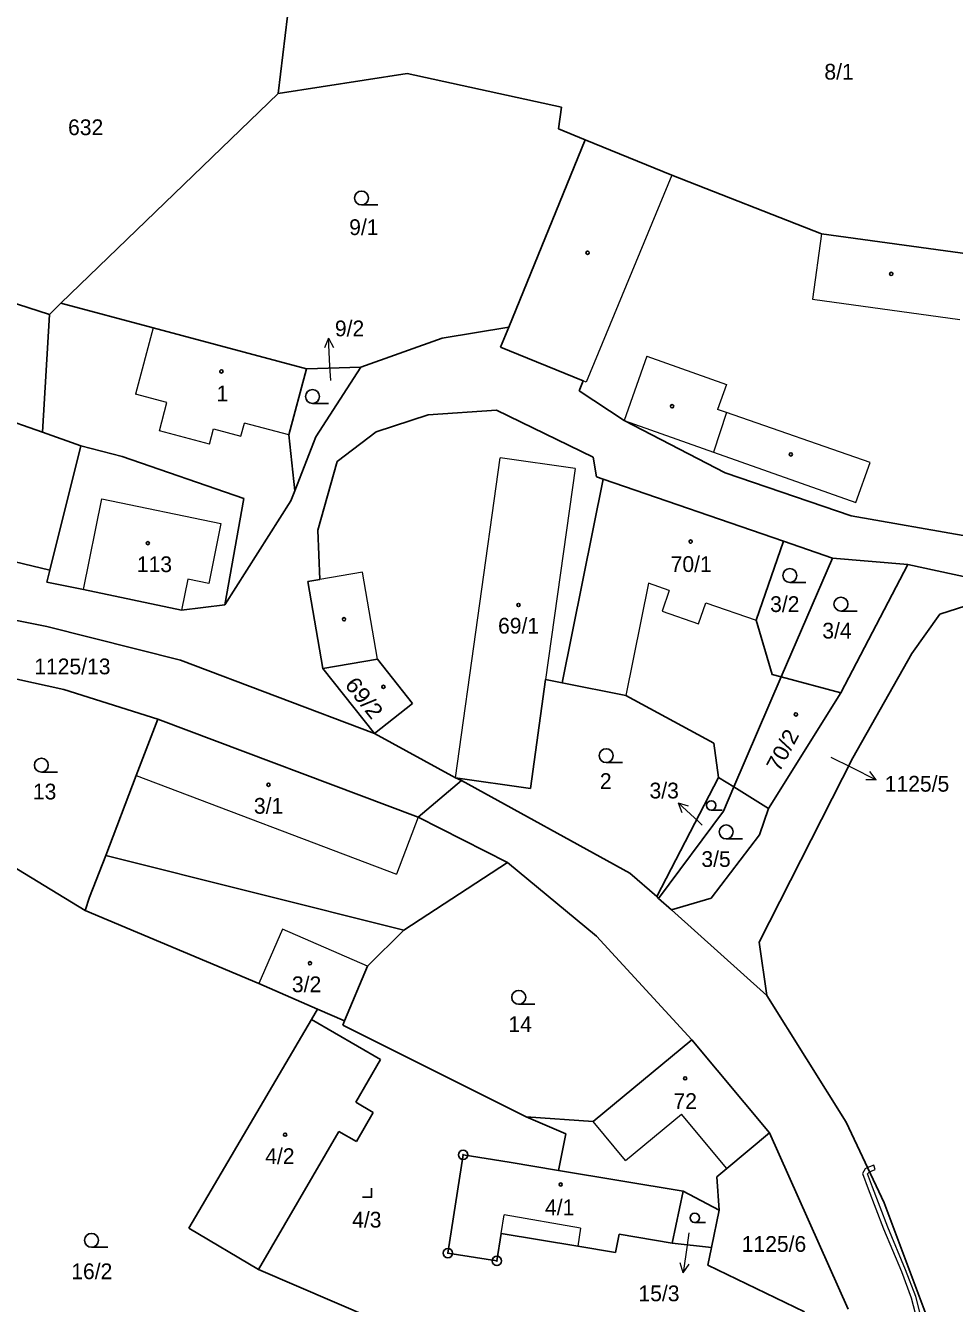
# Model space of a CAD drawing. Extents: x -765428 to -762163, y -1107632 to -1104975.
# Drawn here: x -764228.5 to -764128.3, y -1106034.3 to -1105896.5 of the extents above; entities that cross this region are included whole.
import ezdxf
from ezdxf.enums import TextEntityAlignment as Align

# ---------------------------------------------------------------- set-up
doc = ezdxf.new("R2010")
doc.units = 0
doc.header["$LTSCALE"] = 0.68
for name, color, linetype, lineweight in [('1', 7, 'Continuous', 25), ('13', 7, 'Continuous', 13), ('3', 7, 'Continuous', 25), ('4', 7, 'Continuous', 13), ('5', 7, 'Continuous', 25), ('7', 7, 'Continuous', 13), ('8', 7, 'Continuous', 25)]:
    doc.layers.add(name, color=color, linetype=linetype, lineweight=lineweight)
doc.layers.add('2', color=7, linetype='Continuous')

msp = doc.modelspace()

# ---------------------------------------------------------------- linework, layer by layer
at = {"layer": '1'}
for p, q in [((-764199.41, -1105888.5), (-764201.24, -1105903.77)), ((-764201.24, -1105903.77), (-764187.33, -1105901.63)), ((-764187.33, -1105901.63), (-764170.7, -1105905.25)), ((-764224.66, -1105926.41), (-764201.24, -1105903.77)), ((-764170.7, -1105905.25), (-764171.03, -1105907.61)), ((-764171.03, -1105907.61), (-764168.14, -1105908.79)), ((-764158.81, -1105912.59), (-764168.14, -1105908.79)), ((-764142.66, -1105918.92), (-764158.81, -1105912.59)), ((-764126.68, -1105921.13), (-764142.66, -1105918.92)), ((-764231.82, -1105925.72), (-764225.9, -1105927.61)), ((-764225.9, -1105927.61), (-764224.66, -1105926.41)), ((-764224.66, -1105926.41), (-764214.7, -1105929.07)), ((-764226.64, -1105940.33), (-764260.88, -1105928.31)), ((-764225.9, -1105927.61), (-764226.64, -1105940.33)), ((-764198.19, -1105933.47), (-764214.7, -1105929.07)), ((-764177.25, -1105931.16), (-764176.37, -1105929)), ((-764183.54, -1105930.16), (-764192.34, -1105933.29)), ((-764168.36, -1105934.78), (-764177.25, -1105931.16)), ((-764198.19, -1105933.47), (-764200.1, -1105940.62)), ((-764192.34, -1105933.29), (-764198.19, -1105933.47)), ((-764192.34, -1105933.29), (-764197.16, -1105940.83)), ((-764168.79, -1105935.85), (-764168.36, -1105934.78)), ((-764168.79, -1105935.85), (-764163.94, -1105939.06)), ((-764177.68, -1105937.93), (-764185.08, -1105938.43)), ((-764167.26, -1105943.02), (-764177.68, -1105937.93)), ((-764185.08, -1105938.43), (-764190.68, -1105940.28)), ((-764153.05, -1105944.69), (-764163.94, -1105939.06)), ((-764222.5, -1105941.78), (-764226.64, -1105940.33)), ((-764200.1, -1105940.62), (-764199.44, -1105946.63)), ((-764197.16, -1105940.83), (-764199.44, -1105946.63)), ((-764190.68, -1105940.28), (-764194.87, -1105943.49)), ((-764222.5, -1105941.78), (-764225.85, -1105955.21)), ((-764218.06, -1105942.93), (-764222.5, -1105941.78)), ((-764204.93, -1105947.46), (-764218.06, -1105942.93)), ((-764194.87, -1105943.49), (-764196.97, -1105950.9)), ((-764166.9, -1105945.13), (-764167.26, -1105943.02)), ((-764166.2, -1105945.37), (-764166.9, -1105945.13)), ((-764139.46, -1105949.34), (-764153.05, -1105944.69)), ((-764170.62, -1105967.34), (-764166.2, -1105945.37)), ((-764166.2, -1105945.37), (-764146.77, -1105952.07)), ((-764206.99, -1105958.94), (-764204.93, -1105947.46)), ((-764199.88, -1105947.74), (-764206.99, -1105958.94)), ((-764199.44, -1105946.63), (-764199.88, -1105947.74)), ((-764126.77, -1105951.58), (-764139.46, -1105949.34)), ((-764240.7, -1105951.61), (-764225.85, -1105955.21)), ((-764196.97, -1105950.9), (-764196.75, -1105956.21)), ((-764146.77, -1105952.07), (-764149.71, -1105960.6)), ((-764146.77, -1105952.07), (-764141.47, -1105953.9)), ((-764141.47, -1105953.9), (-764147, -1105966.72)), ((-764141.47, -1105953.9), (-764133.34, -1105954.59)), ((-764133.34, -1105954.59), (-764140.59, -1105968.43)), ((-764133.34, -1105954.59), (-764123.59, -1105956.71)), ((-764225.85, -1105955.21), (-764226.17, -1105956.48)), ((-764226.17, -1105956.48), (-764222.23, -1105957.3)), ((-764211.64, -1105959.51), (-764222.23, -1105957.3)), ((-764196.75, -1105956.21), (-764198.05, -1105956.44)), ((-764198.05, -1105956.44), (-764196.43, -1105965.81)), ((-764239.49, -1105958.6), (-764226.16, -1105961.28)), ((-764211.64, -1105959.51), (-764206.99, -1105958.94)), ((-764129.91, -1105959.96), (-764125.31, -1105958.48)), ((-764132.92, -1105964.2), (-764129.91, -1105959.96)), ((-764226.16, -1105961.28), (-764211.77, -1105964.9)), ((-764139.27, -1105975.43), (-764132.92, -1105964.2)), ((-764211.77, -1105964.9), (-764190.86, -1105972.83)), ((-764190.52, -1105964.79), (-764196.43, -1105965.81)), ((-764196.43, -1105965.81), (-764190.86, -1105972.83)), ((-764190.52, -1105964.79), (-764186.75, -1105969.57)), ((-764224.35, -1105968.07), (-764229.42, -1105966.96)), ((-764172.41, -1105966.98), (-764174.05, -1105978.74)), ((-764172.41, -1105966.98), (-764170.62, -1105967.34)), ((-764147, -1105966.72), (-764152.11, -1105978.58)), ((-764140.59, -1105968.43), (-764147, -1105966.72)), ((-764214.2, -1105971.28), (-764224.35, -1105968.07)), ((-764163.76, -1105968.72), (-764170.62, -1105967.34)), ((-764140.59, -1105968.43), (-764148.38, -1105980.91)), ((-764186.75, -1105969.57), (-764190.86, -1105972.83)), ((-764163.76, -1105968.72), (-764154.27, -1105973.85)), ((-764216.56, -1105977.35), (-764214.2, -1105971.28)), ((-764214.2, -1105971.28), (-764186.14, -1105981.85)), ((-764190.86, -1105972.83), (-764182.12, -1105977.61)), ((-764154.27, -1105973.85), (-764153.75, -1105977.56)), ((-764149.39, -1105995.34), (-764139.27, -1105975.43)), ((-764219.82, -1105985.97), (-764216.56, -1105977.35)), ((-764186.14, -1105981.85), (-764181.47, -1105977.89)), ((-764182.12, -1105977.61), (-764181.47, -1105977.89)), ((-764174.05, -1105978.74), (-764182.12, -1105977.61)), ((-764163.34, -1105987.9), (-764181.47, -1105977.89)), ((-764153.75, -1105977.56), (-764160.43, -1105990.42)), ((-764152.11, -1105978.58), (-764153.75, -1105977.56)), ((-764152.11, -1105978.58), (-764153.24, -1105981.19)), ((-764148.38, -1105980.91), (-764152.11, -1105978.58)), ((-764149.33, -1105983.77), (-764148.38, -1105980.91)), ((-764186.14, -1105981.85), (-764176.51, -1105986.72)), ((-764153.24, -1105981.19), (-764160.22, -1105990.61)), ((-764222.03, -1105991.92), (-764237.59, -1105982.48)), ((-764154.57, -1105990.6), (-764149.33, -1105983.77)), ((-764221.58, -1105990.48), (-764219.82, -1105985.97)), ((-764176.51, -1105986.72), (-764187.69, -1105994.03)), ((-764166.91, -1105994.67), (-764176.51, -1105986.72)), ((-764160.43, -1105990.42), (-764163.34, -1105987.9)), ((-764222.03, -1105991.92), (-764221.58, -1105990.48)), ((-764160.43, -1105990.42), (-764160.22, -1105990.61)), ((-764160.22, -1105990.61), (-764158.83, -1105991.86)), ((-764158.83, -1105991.86), (-764154.57, -1105990.6)), ((-764203.33, -1105999.8), (-764222.03, -1105991.92)), ((-764148.54, -1106001.09), (-764158.83, -1105991.86)), ((-764156.65, -1106005.88), (-764166.91, -1105994.67)), ((-764148.54, -1106001.09), (-764149.39, -1105995.34)), ((-764191.6, -1105997.92), (-764194.08, -1106003.83)), ((-764203.33, -1105999.8), (-764196.98, -1106002.57)), ((-764140, -1106014.74), (-764148.54, -1106001.09)), ((-764196.98, -1106002.57), (-764197.63, -1106003.67)), ((-764196.98, -1106002.57), (-764194.08, -1106003.83)), ((-764197.63, -1106003.67), (-764210.85, -1106026.19)), ((-764197.63, -1106003.67), (-764190.2, -1106007.97)), ((-764194.27, -1106004.27), (-764194.08, -1106003.83)), ((-764194.27, -1106004.27), (-764174.49, -1106014.16)), ((-764167.28, -1106014.68), (-764156.65, -1106005.88)), ((-764148.26, -1106015.89), (-764156.65, -1106005.88)), ((-764192.87, -1106012.58), (-764190.2, -1106007.97)), ((-764191, -1106013.7), (-764192.87, -1106012.58)), ((-764191, -1106013.7), (-764192.79, -1106016.83)), ((-764174.49, -1106014.16), (-764170.24, -1106016.01)), ((-764174.49, -1106014.16), (-764167.28, -1106014.68)), ((-764194.71, -1106015.75), (-764203.35, -1106030.65)), ((-764192.79, -1106016.83), (-764194.71, -1106015.75)), ((-764170.24, -1106016.01), (-764171, -1106019.95)), ((-764152.85, -1106019.74), (-764148.26, -1106015.89)), ((-764148.26, -1106015.89), (-764139.79, -1106034.92)), ((-764181.3, -1106018.27), (-764182.94, -1106028.87)), ((-764176.34, -1106019.06), (-764181.3, -1106018.27)), ((-764171, -1106019.95), (-764176.34, -1106019.06)), ((-764157.59, -1106022.2), (-764171, -1106019.95)), ((-764153.93, -1106020.64), (-764152.85, -1106019.74)), ((-764153.93, -1106020.64), (-764153.69, -1106024.23)), ((-764158.75, -1106027.8), (-764157.59, -1106022.2)), ((-764157.59, -1106022.2), (-764153.69, -1106024.23)), ((-764153.69, -1106024.23), (-764154.53, -1106028.28)), ((-764210.85, -1106026.19), (-764203.35, -1106030.65)), ((-764177.66, -1106029.71), (-764177.19, -1106026.75)), ((-764177.19, -1106026.75), (-764168.92, -1106028.14)), ((-764164.86, -1106028.8), (-764164.48, -1106026.82)), ((-764164.48, -1106026.82), (-764158.75, -1106027.8)), ((-764154.53, -1106028.28), (-764158.75, -1106027.8)), ((-764182.94, -1106028.87), (-764177.66, -1106029.71)), ((-764168.92, -1106028.14), (-764164.86, -1106028.8)), ((-764154.92, -1106030.18), (-764154.53, -1106028.28)), ((-764144.5, -1106035.19), (-764154.92, -1106030.18)), ((-764203.35, -1106030.65), (-764191.08, -1106035.94))]:
    msp.add_line(p, q, dxfattribs=at)
for points in [[(-764183.54, -1105930.16), (-764176.37, -1105929), (-764168.14, -1105908.79)], [(-764147, -1105966.72), (-764147.97, -1105966.46), (-764149.71, -1105960.6)], [(-764219.82, -1105985.97), (-764187.69, -1105994.03), (-764191.6, -1105997.92)], [(-764129.85, -1106039.54), (-764135.9, -1106023.45), (-764140, -1106014.74)]]:
    msp.add_lwpolyline(points, dxfattribs=at)
at = {"layer": '13'}
msp.add_lwpolyline([(-764137.48, -1106020.1), (-764136.87, -1106019.86), (-764137.03, -1106019.39), (-764137.5, -1106019.55), (-764137.69, -1106019.65)], close=True, dxfattribs=at)
msp.add_lwpolyline([(-764131.41, -1106037.84), (-764132.5, -1106033.55), (-764133.59, -1106030.67), (-764135.52, -1106026.08), (-764137.17, -1106021.77), (-764137.69, -1106020.33), (-764137.48, -1106020.1), (-764137.69, -1106019.65), (-764137.95, -1106019.78), (-764138.25, -1106020.27), (-764137.63, -1106021.95), (-764135.98, -1106026.26), (-764134.05, -1106030.85), (-764132.98, -1106033.71), (-764131.89, -1106037.96)], dxfattribs=at)
at = {"layer": '3'}
for p, q in [((-764192.243, -1105915.81), (-764190.493, -1105915.81)), ((-764197.543, -1105937.22), (-764195.793, -1105937.22)), ((-764146.083, -1105956.53), (-764144.333, -1105956.53)), ((-764140.563, -1105959.61), (-764138.813, -1105959.61)), ((-764165.873, -1105975.96), (-764164.123, -1105975.96)), ((-764226.763, -1105976.98), (-764225.013, -1105976.98)), ((-764154.545, -1105981.08), (-764153.373, -1105981.08)), ((-764152.933, -1105984.19), (-764151.183, -1105984.19)), ((-764175.303, -1106002.03), (-764173.553, -1106002.03)), ((-764156.325, -1106025.57), (-764155.153, -1106025.57)), ((-764221.353, -1106028.24), (-764219.603, -1106028.24))]:
    msp.add_line(p, q, dxfattribs=at)
msp.add_lwpolyline([(-764192.161, -1106022.85), (-764191.16, -1106022.85), (-764191.16, -1106021.85)], dxfattribs=at)
for centre, radius in [((-764192.2429, -1105915.0598), 0.75), ((-764197.5429, -1105936.4698), 0.75), ((-764146.0829, -1105955.7798), 0.75), ((-764140.5629, -1105958.8598), 0.75), ((-764226.7629, -1105976.2298), 0.75), ((-764165.8729, -1105975.2098), 0.75), ((-764154.5452, -1105980.5774), 0.5025), ((-764152.9329, -1105983.4398), 0.75), ((-764175.3029, -1106001.2798), 0.75), ((-764156.3252, -1106025.0674), 0.5025), ((-764221.3529, -1106027.4898), 0.75)]:
    msp.add_circle(centre, radius, dxfattribs=at)
at = {"layer": '4'}
for p, q in [((-764158.81, -1105912.59), (-764168.03, -1105934.91)), ((-764142.66, -1105918.92), (-764143.63, -1105925.97)), ((-764143.63, -1105925.97), (-764127.75, -1105928.18)), ((-764214.7, -1105929.07), (-764216.61, -1105936.22)), ((-764161.5, -1105932.13), (-764163.94, -1105939.06)), ((-764168.03, -1105934.91), (-764168.36, -1105934.78)), ((-764213.23, -1105937.12), (-764216.61, -1105936.22)), ((-764152.91, -1105938.2), (-764154.3, -1105942.47)), ((-764152.91, -1105938.2), (-764153.86, -1105937.87)), ((-764137.43, -1105943.59), (-764152.91, -1105938.2)), ((-764200.1, -1105940.62), (-764204.88, -1105939.34)), ((-764163.94, -1105939.06), (-764154.3, -1105942.47)), ((-764208.63, -1105941.61), (-764208.19, -1105939.97)), ((-764182.12, -1105977.61), (-764177.3, -1105943.1)), ((-764169.23, -1105944.23), (-764177.3, -1105943.1)), ((-764154.3, -1105942.47), (-764138.96, -1105947.9)), ((-764138.96, -1105947.9), (-764137.43, -1105943.59)), ((-764169.23, -1105944.23), (-764172.41, -1105966.98)), ((-764222.23, -1105957.3), (-764220.24, -1105947.51)), ((-764220.24, -1105947.51), (-764207.41, -1105950.16)), ((-764207.41, -1105950.16), (-764208.71, -1105956.63)), ((-764210.97, -1105956.17), (-764211.64, -1105959.51)), ((-764208.71, -1105956.63), (-764210.97, -1105956.17)), ((-764192.14, -1105955.42), (-764196.75, -1105956.21)), ((-764190.52, -1105964.79), (-764192.14, -1105955.42)), ((-764161.32, -1105956.6), (-764163.76, -1105968.72)), ((-764159.07, -1105957.38), (-764161.32, -1105956.6)), ((-764155.13, -1105958.74), (-764149.71, -1105960.6)), ((-764216.56, -1105977.35), (-764188.48, -1105987.99)), ((-764186.14, -1105981.85), (-764188.48, -1105987.99)), ((-764200.76, -1105993.91), (-764203.33, -1105999.8)), ((-764191.6, -1105997.92), (-764200.76, -1105993.91)), ((-764163.79, -1106018.89), (-764157.75, -1106013.89)), ((-764152.85, -1106019.74), (-764157.75, -1106013.89)), ((-764163.79, -1106018.89), (-764167.28, -1106014.68)), ((-764177.19, -1106026.75), (-764176.88, -1106024.75)), ((-764168.65, -1106026.18), (-764176.88, -1106024.75)), ((-764168.65, -1106026.18), (-764168.92, -1106028.14))]:
    msp.add_line(p, q, dxfattribs=at)
for points in [[(-764161.5, -1105932.13), (-764152.9, -1105935.17), (-764153.86, -1105937.87)], [(-764208.63, -1105941.61), (-764214.04, -1105940.16), (-764213.23, -1105937.12)], [(-764208.19, -1105939.97), (-764205.26, -1105940.76), (-764204.88, -1105939.34)], [(-764159.07, -1105957.38), (-764159.85, -1105959.64), (-764155.91, -1105961), (-764155.13, -1105958.74)]]:
    msp.add_lwpolyline(points, dxfattribs=at)
at = {"layer": '5'}
for centre in [(-764167.8768, -1105920.9592), (-764135.1468, -1105923.2392), (-764207.3568, -1105933.7692), (-764158.7668, -1105937.5192), (-764145.9668, -1105942.7192), (-764156.7668, -1105952.1192), (-764215.2868, -1105952.2892), (-764175.3268, -1105958.9592), (-764194.1368, -1105960.4992), (-764189.8868, -1105967.7892), (-764145.4168, -1105970.7692), (-764202.2768, -1105978.3492), (-764197.8068, -1105997.5992), (-764157.3568, -1106010.0192), (-764200.4868, -1106016.0992), (-764170.7768, -1106021.4692)]:
    msp.add_circle(centre, 0.175, dxfattribs=at)
at = {"layer": '7'}
for p, q in [((-764195.807, -1105930.193), (-764196.255, -1105931.219)), ((-764136.776, -1105977.822), (-764137.441, -1105976.922)), ((-764158.095, -1105980.303), (-764157.704, -1105981.353)), ((-764157.558, -1106030.982), (-764156.922, -1106030.06))]:
    msp.add_line(p, q, dxfattribs=at)
for points in [[(-764195.57, -1105934.74), (-764195.65, -1105933.19), (-764195.807, -1105930.193), (-764195.255, -1105931.167)], [(-764141.65, -1105975.36), (-764139.45, -1105976.46), (-764136.776, -1105977.822), (-764137.896, -1105977.814)], [(-764155.51, -1105982.71), (-764155.9, -1105982.35), (-764158.095, -1105980.303), (-764157.021, -1105980.62)], [(-764156.95, -1106026.67), (-764157.14, -1106028.01), (-764157.558, -1106030.982), (-764157.914, -1106029.92)]]:
    msp.add_lwpolyline(points, dxfattribs=at)
at = {"layer": '8'}
for centre, radius in [((-764181.3, -1106018.2699), 0.5), ((-764181.3, -1106018.2699), 0.0303), ((-764182.94, -1106028.8699), 0.5), ((-764182.94, -1106028.8699), 0.0303), ((-764177.66, -1106029.7099), 0.5), ((-764177.66, -1106029.7099), 0.0303)]:
    msp.add_circle(centre, radius, dxfattribs=at)

# ---------------------------------------------------------------- texts
at = {"layer": '2'}
for s, p in [('8/1', (-764140.77, -1105902.285)), ('632', (-764221.989, -1105908.275))]:
    msp.add_text(s, height=1.7, dxfattribs=at).set_placement(p, align=Align.CENTER)
for s, p in [('9/1', (-764193.58, -1105919.055)), ('1', (-764207.88, -1105936.985)), ('113', (-764216.47, -1105955.415)), ('70/1', (-764158.92, -1105955.395)), ('3/2', (-764148.2, -1105959.715)), ('69/1', (-764177.53, -1105962.045)), ('3/4', (-764142.57, -1105962.575)), ('1125/13', (-764227.53, -1105966.435)), ('13', (-764227.68, -1105979.935)), ('2', (-764166.55, -1105978.805)), ('1125/5', (-764135.84, -1105979.095)), ('3/1', (-764203.85, -1105981.475)), ('3/5', (-764155.61, -1105987.215)), ('3/2', (-764199.75, -1106000.725)), ('14', (-764176.41, -1106005.025)), ('72', (-764158.62, -1106013.325)), ('4/2', (-764202.63, -1106019.265)), ('4/1', (-764172.47, -1106024.785)), ('4/3', (-764193.26, -1106026.115)), ('1125/6', (-764151.26, -1106028.735)), ('16/2', (-764223.54, -1106031.685))]:
    msp.add_text(s, height=1.7, dxfattribs=at).set_placement(p)
for s, p in [('9/2', (-764191.959, -1105929.975)), ('3/3', (-764158.039, -1105979.825)), ('15/3', (-764157.969, -1106034.065))]:
    msp.add_text(s, height=1.7, dxfattribs=at).set_placement(p, align=Align.RIGHT)
for s, rotation, width, p in [('69/2', 308, 1.1, (-764194.134, -1105967.581)), ('70/2', 62, 1.05, (-764147.194, -1105977.069))]:
    msp.add_text(s, height=1.7, rotation=rotation, dxfattribs=dict(at, width=width)).set_placement(p)

doc.saveas('drawing.dxf')
